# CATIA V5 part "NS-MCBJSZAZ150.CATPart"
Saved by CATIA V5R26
Part number: NS-MCBJSZAZ150
Bounding box of the stored display mesh (mm): x -60 to 120, y 0 to 198, z -110.177 to 60
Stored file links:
  R:\Document\坂尻\その他\ナベヤデータ変換\安全カバーキャスター\MCBJSZAZ150\NS-MCBJSZAZ150.CATPart
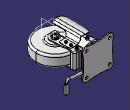
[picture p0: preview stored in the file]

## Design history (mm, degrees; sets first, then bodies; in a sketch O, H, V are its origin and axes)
Body1 (main body)
  Solid1: solid without history
  Body2
    Solid2: solid without history
  Assemble1: tool Body2
  Body3
    Solid3: solid without history
  Assemble2: tool Body3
